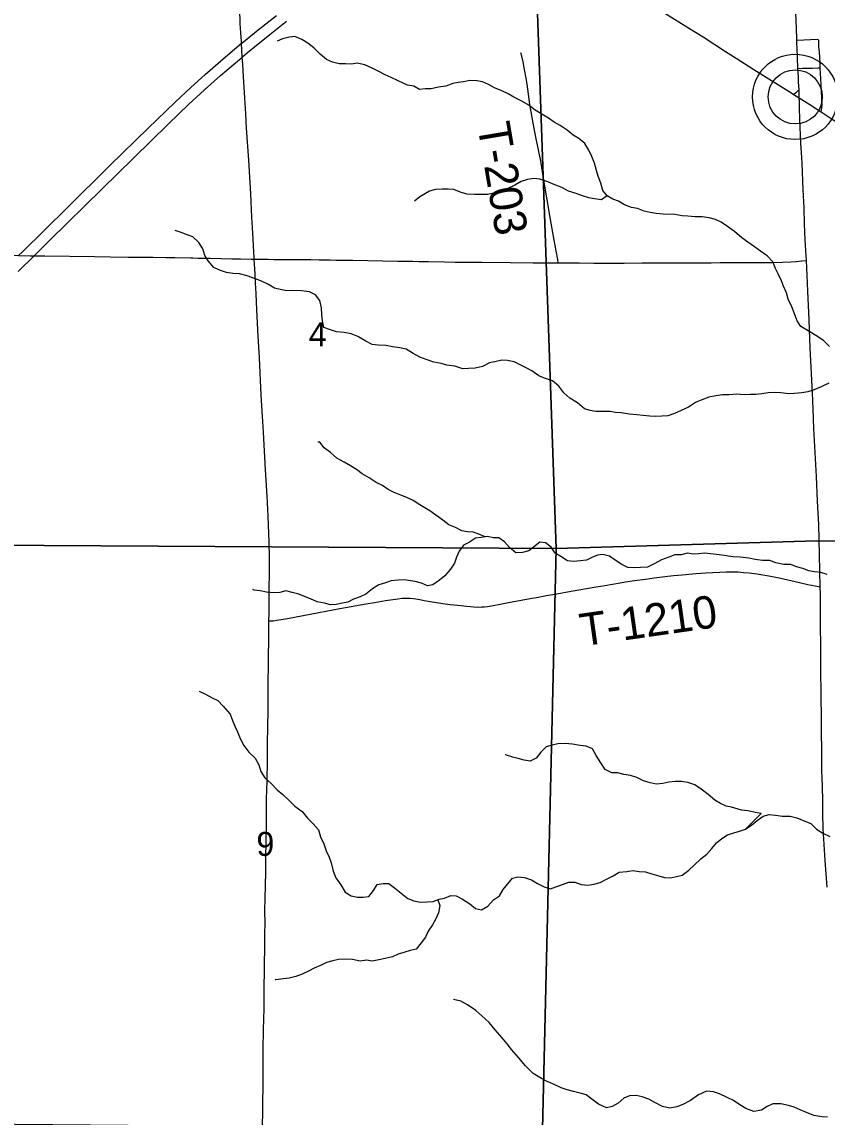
# Model space of a CAD drawing. Extents: x 0 to 34, y 0 to 22.
# Drawn here: x 13.666 to 15.07, y 11.289 to 13.199 of the extents above; entities that cross this region are included whole.
import ezdxf

# ---------------------------------------------------------------- set-up
doc = ezdxf.new("R2010")
doc.units = 0
for name, color, linetype in [('GM_X_County_Road', 7, 'Continuous'), ('GM_X_Interstate_Route', 7, 'Continuous'), ('GM_X_Minor_River', 7, 'Continuous'), ('GM_X_Section', 7, 'Continuous'), ('GM_X_Section_Text', 7, 'Continuous'), ('GM_X_State_Route', 7, 'Continuous'), ('GM_X_Township_Road', 7, 'Continuous'), ('GM_X_Township_Road_Text', 7, 'Continuous'), ('GM_X_Unincorporated', 7, 'Continuous'), ('GM_X_Unincorporated_Location', 7, 'Continuous')]:
    doc.layers.add(name, color=color, linetype=linetype)

msp = doc.modelspace()

# ---------------------------------------------------------------- linework, layer by layer
at = {"layer": 'GM_X_County_Road'}
msp.add_line((15.0217, 13.066), (15.0214, 13.0811), dxfattribs=at)
for points in [[(15.0175, 13.1667), (15.0173, 13.1721), (15.0166, 13.1852), (15.016, 13.2036), (15.015, 13.2225), (15.0142, 13.2429), (15.0126, 13.2796), (15.0123, 13.2934), (15.0124, 13.3029)], [(14.0708, 12.7856), (14.0707, 12.7876), (14.0685, 12.831), (14.0669, 12.8589), (14.0649, 12.8993), (14.0614, 12.9582), (14.0576, 13.0139), (14.0561, 13.0387), (14.0544, 13.0666), (14.052, 13.1034), (14.0508, 13.1253), (14.0499, 13.1379), (14.0498, 13.1387), (14.0488, 13.1608), (14.0487, 13.1619), (14.0485, 13.1658), (14.0475, 13.1804), (14.0465, 13.1967), (14.0456, 13.2216)], [(15.0193, 13.118), (15.0187, 13.1376), (15.0182, 13.1527), (15.0177, 13.1623), (15.0175, 13.1667)], [(15.0214, 13.0811), (15.0206, 13.0943), (15.0201, 13.1028), (15.0193, 13.118)], [(15.0113, 13.0726), (15.0151, 13.0753), (15.0171, 13.0767), (15.0188, 13.0785), (15.0214, 13.0811)], [(15.0342, 12.7829), (15.0337, 12.7914), (15.0322, 12.8194), (15.031, 12.8473), (15.03, 12.8752), (15.0285, 12.9063), (15.0265, 12.9528), (15.0254, 12.9714), (15.0246, 12.9869), (15.0227, 13.0303), (15.0221, 13.0488), (15.0218, 13.0612), (15.0217, 13.066)], [(14.0965, 12.1546), (14.0967, 12.1671), (14.0967, 12.1857), (14.0971, 12.2075), (14.0976, 12.2416), (14.0977, 12.2665), (14.0971, 12.2913), (14.095, 12.3375), (14.0935, 12.3719), (14.0904, 12.4183), (14.087, 12.4836), (14.0853, 12.5115), (14.0832, 12.5485), (14.0798, 12.6132), (14.0777, 12.651), (14.0754, 12.6973), (14.074, 12.7256), (14.073, 12.7442), (14.0722, 12.7597), (14.0708, 12.7856)], [(15.0583, 12.2138), (15.0571, 12.27), (15.0556, 12.3228), (15.0536, 12.3632), (15.0516, 12.4066), (15.0473, 12.4904), (15.0458, 12.5245), (15.0446, 12.5525), (15.0409, 12.6301), (15.0388, 12.6797), (15.0365, 12.7294), (15.0353, 12.7573), (15.0342, 12.7829)], [(15.0704, 11.6906), (15.0668, 11.737), (15.0646, 11.7743), (15.0634, 11.7926), (15.063, 11.8176), (15.0628, 11.8393), (15.062, 11.8675), (15.0617, 11.8796), (15.0613, 11.895), (15.061, 11.9106), (15.0611, 11.923), (15.061, 11.9292), (15.0609, 11.9354), (15.0608, 11.9384), (15.0605, 11.9505), (15.0604, 11.9594), (15.0602, 11.9842), (15.0601, 12.0246), (15.0595, 12.0712), (15.0594, 12.0992), (15.059, 12.1582), (15.0586, 12.2017), (15.0583, 12.2138)], [(14.0854, 11.2733), (14.0858, 11.2997), (14.0861, 11.3183), (14.0862, 11.34), (14.0863, 11.3555), (14.0866, 11.4079), (14.0871, 11.4418), (14.0875, 11.4603), (14.0879, 11.479), (14.0882, 11.5037), (14.0884, 11.5192), (14.0887, 11.5408), (14.0889, 11.5594), (14.0892, 11.581), (14.0895, 11.609), (14.0897, 11.6275), (14.0895, 11.6492), (14.0897, 11.6709), (14.0903, 11.6927), (14.0909, 11.7175), (14.091, 11.7298), (14.0911, 11.7452), (14.0911, 11.7512), (14.0914, 11.7603), (14.0917, 11.7758), (14.092, 11.7943), (14.092, 11.8065), (14.092, 11.8176), (14.092, 11.8251), (14.092, 11.8333), (14.0925, 11.8425), (14.0931, 11.861), (14.0934, 11.8734), (14.0937, 11.9138), (14.0941, 11.9417), (14.0944, 11.9695), (14.0949, 12.0003), (14.095, 12.028), (14.0951, 12.0373), (14.0958, 12.0868), (14.0962, 12.1269), (14.0964, 12.1464), (14.0965, 12.1546)]]:
    msp.add_lwpolyline(points, dxfattribs=at)
at = {"layer": 'GM_X_Interstate_Route'}
for points in [[(13.6592, 12.7639), (13.687, 12.7913), (13.7145, 12.8185), (13.8053, 12.9079), (13.8608, 12.9623), (13.9206, 13.0211), (13.9566, 13.0555), (13.984, 13.0809), (14.012, 13.1056), (14.045, 13.1339), (14.0499, 13.1379), (14.0506, 13.1386), (14.0593, 13.1459), (14.0712, 13.1559), (14.0978, 13.1775), (14.1273, 13.2004)], [(13.6597, 12.7919), (13.6663, 12.7984), (13.7439, 12.8746), (13.8192, 12.9488), (13.886, 13.0138), (13.9329, 13.0591), (13.9601, 13.0846), (13.9855, 13.1075), (14.0205, 13.1381), (14.0487, 13.1619), (14.0494, 13.1624), (14.0779, 13.1856), (14.1097, 13.2105)]]:
    msp.add_lwpolyline(points, dxfattribs=at)
at = {"layer": 'GM_X_Minor_River'}
for points in [[(15.0745, 12.6332), (15.064, 12.6436), (15.0508, 12.6521), (15.0399, 12.659), (15.0245, 12.6683), (15.0181, 12.6782), (15.0125, 12.6919), (15.0085, 12.7022), (15.0025, 12.7159), (14.9992, 12.7266), (14.994, 12.7384), (14.9907, 12.7479), (14.9855, 12.7589), (14.9803, 12.7692), (14.9758, 12.781), (14.9657, 12.791), (14.954, 12.7995), (14.9435, 12.8068), (14.9322, 12.8149), (14.9213, 12.8226), (14.9089, 12.8337), (14.8964, 12.8422), (14.8855, 12.8502), (14.8757, 12.8545), (14.8644, 12.8573), (14.8523, 12.8593), (14.8398, 12.8594), (14.8273, 12.8603), (14.8175, 12.8611), (14.8046, 12.8632), (14.7842, 12.8637), (14.7721, 12.865), (14.7615, 12.867), (14.7513, 12.8694), (14.7392, 12.874), (14.729, 12.8757), (14.7165, 12.88), (14.7063, 12.8865), (14.6962, 12.89), (14.6864, 12.8958), (14.6789, 12.9054), (14.6756, 12.9179), (14.6711, 12.9305), (14.6678, 12.94), (14.6645, 12.9529), (14.6597, 12.9644), (14.6545, 12.9758), (14.6478, 12.9873), (14.6372, 12.9961), (14.6274, 13.0015), (14.6165, 13.0107), (14.6048, 13.0184), (14.5943, 13.0246), (14.5841, 13.0315), (14.5608, 13.0454), (14.5499, 13.0539), (14.5363, 13.0616), (14.5235, 13.0681), (14.5137, 13.0736), (14.5027, 13.079), (14.4899, 13.0844), (14.4794, 13.0898), (14.4688, 13.0945), (14.459, 13.0965), (14.4472, 13.097), (14.4362, 13.0948), (14.4268, 13.0938), (14.4173, 13.0916), (14.4051, 13.0871), (14.3922, 13.0857), (14.3793, 13.0825), (14.3691, 13.0826), (14.3593, 13.0815), (14.3491, 13.0869), (14.3385, 13.0889), (14.3219, 13.0963), (14.3098, 13.1021), (14.2993, 13.1068), (14.2868, 13.1133), (14.2766, 13.1187), (14.2638, 13.1242), (14.2506, 13.127), (14.2403, 13.1255), (14.2301, 13.126), (14.2188, 13.1261), (14.2071, 13.1293), (14.1969, 13.1339), (14.1856, 13.1428), (14.1747, 13.1539), (14.1645, 13.1623), (14.154, 13.1685), (14.1419, 13.1736), (14.1321, 13.1725), (14.1203, 13.17), (14.1108, 13.1659)], [(14.6864, 12.8958), (14.6768, 12.8891), (14.6647, 12.8907), (14.6545, 12.8927), (14.6436, 12.8962), (14.6326, 12.9001), (14.619, 12.9041), (14.6073, 12.9106), (14.5953, 12.9153), (14.5828, 12.9203), (14.5692, 12.925), (14.5586, 12.9263), (14.5476, 12.9245), (14.5366, 12.9212), (14.5252, 12.9145), (14.5134, 12.9085), (14.5024, 12.9048), (14.4918, 12.9011), (14.4777, 12.8982), (14.466, 12.898), (14.455, 12.8981), (14.4425, 12.8986), (14.4319, 12.9017), (14.4191, 12.9071), (14.4093, 12.9076), (14.3987, 12.9073), (14.3869, 12.9067), (14.3767, 12.9038), (14.3599, 12.8941), (14.3504, 12.8869)], [(14.2658, 12.6423), (14.2515, 12.6504), (14.2398, 12.6554), (14.2277, 12.6574), (14.2144, 12.6587), (14.2039, 12.6622), (14.1925, 12.6665), (14.19, 12.6779), (14.1889, 12.6885), (14.1879, 12.7007), (14.185, 12.7132), (14.1775, 12.7232), (14.1673, 12.7286), (14.1533, 12.7302), (14.1382, 12.7308), (14.1276, 12.7301), (14.1158, 12.7325), (14.106, 12.7349), (14.0958, 12.7411), (14.0834, 12.7469), (14.0728, 12.7511), (14.0585, 12.7562), (14.0453, 12.7601), (14.0335, 12.7606), (14.0222, 12.7623), (14.012, 12.7658), (14.0003, 12.7708), (13.9902, 12.7823), (13.9849, 12.7918), (13.9809, 12.8033), (13.9742, 12.8143), (13.964, 12.8243), (13.9538, 12.8282), (13.9436, 12.8317), (13.9331, 12.8356)], [(15.0732, 12.5691), (15.0599, 12.5628), (15.0462, 12.5572), (15.0364, 12.5543), (15.0261, 12.5525), (15.0136, 12.5511), (15.0034, 12.5508), (14.9894, 12.5521), (14.9784, 12.553), (14.9674, 12.5523), (14.9564, 12.5505), (14.9458, 12.5495), (14.9356, 12.5496), (14.9258, 12.5489), (14.9129, 12.5498), (14.8996, 12.5488), (14.8875, 12.5489), (14.8761, 12.5471), (14.864, 12.5446), (14.8515, 12.5402), (14.8404, 12.5353), (14.8286, 12.5275), (14.8157, 12.5215), (14.8039, 12.5163), (14.7922, 12.5123), (14.7819, 12.5116), (14.7706, 12.511), (14.7607, 12.5118), (14.7494, 12.5131), (14.7384, 12.5139), (14.7252, 12.5152), (14.7112, 12.5176), (14.7013, 12.5181), (14.6915, 12.5197), (14.6669, 12.52), (14.6571, 12.5216), (14.6472, 12.5243), (14.6348, 12.5347), (14.6216, 12.5432), (14.6111, 12.5524), (14.6025, 12.5638), (14.5912, 12.5734), (14.5773, 12.5781), (14.5671, 12.582), (14.555, 12.5905), (14.5452, 12.5959), (14.5347, 12.6013), (14.5241, 12.6063), (14.5124, 12.6087), (14.5025, 12.6092), (14.4908, 12.6063), (14.4813, 12.6049), (14.4688, 12.5982), (14.4562, 12.5952), (14.4445, 12.5946), (14.4346, 12.5943), (14.421, 12.599), (14.4067, 12.6007), (14.3968, 12.6034), (14.384, 12.6058), (14.3723, 12.6097), (14.3595, 12.6144), (14.3482, 12.621), (14.3357, 12.6283), (14.3248, 12.6311), (14.3123, 12.6327), (14.3009, 12.6351), (14.2873, 12.6356), (14.2767, 12.6368), (14.2658, 12.6423)], [(14.4738, 12.3012), (14.4625, 12.3057), (14.4527, 12.3092), (14.4428, 12.31), (14.433, 12.3116), (14.4217, 12.3174), (14.4104, 12.3221), (14.3998, 12.3302), (14.3878, 12.339), (14.3769, 12.3467), (14.3595, 12.3571), (14.3483, 12.3648), (14.3373, 12.3699), (14.3267, 12.3738), (14.315, 12.3784), (14.3045, 12.3839), (14.2947, 12.3908), (14.2834, 12.3958), (14.2713, 12.4039), (14.2593, 12.4112), (14.2495, 12.4185), (14.2389, 12.4251), (14.228, 12.4313), (14.2148, 12.4382), (14.2039, 12.4482), (14.193, 12.4567), (14.1852, 12.4662), (14.1817, 12.4666)], [(15.0704, 12.2356), (15.0591, 12.2388), (15.0485, 12.24), (15.0386, 12.242), (15.0281, 12.2459), (15.0167, 12.2487), (15.0069, 12.2529), (14.9948, 12.253), (14.9808, 12.2558), (14.9706, 12.2601), (14.9578, 12.2599), (14.9449, 12.2619), (14.9336, 12.2643), (14.9184, 12.2659), (14.9059, 12.2664), (14.895, 12.2684), (14.8817, 12.2697), (14.8666, 12.2714), (14.8564, 12.2726), (14.8465, 12.2719), (14.8363, 12.2713), (14.8265, 12.2729), (14.8158, 12.27), (14.8045, 12.2697), (14.7942, 12.266), (14.7813, 12.2612), (14.7695, 12.2545), (14.757, 12.2485), (14.7445, 12.2479), (14.7342, 12.2472), (14.7225, 12.2477), (14.7119, 12.2528), (14.7007, 12.2605), (14.6905, 12.2678), (14.6792, 12.2705), (14.6697, 12.2695), (14.6598, 12.2654), (14.6503, 12.2606), (14.6393, 12.2592), (14.6279, 12.2585), (14.6173, 12.2594), (14.606, 12.2667), (14.5959, 12.2729), (14.5888, 12.2832), (14.579, 12.2909), (14.5688, 12.2921), (14.5497, 12.2771), (14.5391, 12.2742), (14.527, 12.2735), (14.5161, 12.2824), (14.5074, 12.2923), (14.4973, 12.2996), (14.4874, 12.2997), (14.4776, 12.3017), (14.467, 12.3003), (14.4571, 12.2989), (14.4461, 12.2922), (14.4362, 12.2866), (14.4282, 12.276), (14.4235, 12.2658)], [(14.4235, 12.2658), (14.4204, 12.2552), (14.4131, 12.2451), (14.4036, 12.233), (14.394, 12.2259), (14.3826, 12.2176), (14.3731, 12.2158), (14.3629, 12.2205), (14.3516, 12.2236), (14.3319, 12.2261), (14.3217, 12.2258), (14.31, 12.2248), (14.2997, 12.2211), (14.2883, 12.2174), (14.2773, 12.2107), (14.2658, 12.2013), (14.2556, 12.1965), (14.2438, 12.1924), (14.2343, 12.1872), (14.2248, 12.1858), (14.2138, 12.1832), (14.204, 12.1826), (14.1934, 12.1853), (14.1809, 12.1877), (14.1692, 12.1932), (14.1586, 12.1974), (14.1484, 12.2013), (14.1371, 12.2041), (14.1262, 12.2072), (14.1155, 12.2039), (14.1053, 12.2037), (14.0924, 12.2049), (14.0811, 12.2073), (14.0705, 12.2082), (14.0686, 12.2097)], [(13.9747, 12.0319), (13.986, 12.0269), (13.9973, 12.0203), (14.0075, 12.0156), (14.0165, 12.0061), (14.0289, 11.9919), (14.033, 11.9809), (14.0371, 11.9713), (14.0415, 11.9614), (14.0463, 11.9496), (14.0527, 11.9374), (14.0617, 11.9259), (14.0722, 11.9152), (14.0789, 11.9034), (14.0826, 11.892), (14.0893, 11.8809), (14.1002, 11.8709), (14.1107, 11.8602), (14.1209, 11.8518), (14.131, 11.8418), (14.1415, 11.8318), (14.1543, 11.8222), (14.1637, 11.8104), (14.1738, 11.8008), (14.1832, 11.7904), (14.1865, 11.7779), (14.1925, 11.7657), (14.1965, 11.7539), (14.2013, 11.7424), (14.2051, 11.7325), (14.2087, 11.7181), (14.2132, 11.7067), (14.2221, 11.6941), (14.2292, 11.6815), (14.2402, 11.6753), (14.2511, 11.6729), (14.261, 11.6728), (14.2708, 11.6742), (14.2789, 11.6844), (14.2854, 11.695), (14.296, 11.6967), (14.3059, 11.6967), (14.3156, 11.6893), (14.3269, 11.6801), (14.3386, 11.6705), (14.3495, 11.6663), (14.3609, 11.6642), (14.3726, 11.6645), (14.3832, 11.6655), (14.3935, 11.6692), (14.4029, 11.671), (14.4136, 11.6759), (14.4234, 11.6754), (14.4344, 11.6692), (14.4468, 11.6611), (14.4566, 11.6534), (14.4671, 11.6507), (14.4782, 11.657), (14.4881, 11.6683), (14.4988, 11.675), (14.5053, 11.686), (14.5134, 11.6961), (14.5214, 11.7059), (14.5309, 11.7085), (14.5422, 11.7069), (14.5547, 11.703), (14.5649, 11.6968), (14.5769, 11.691), (14.5875, 11.6875), (14.597, 11.6908), (14.6088, 11.6952), (14.6198, 11.6993), (14.63, 11.6988), (14.6409, 11.6949), (14.6531, 11.6936), (14.6633, 11.6954), (14.6743, 11.6984), (14.6853, 11.7043), (14.6971, 11.7103), (14.7074, 11.7163), (14.7207, 11.7177), (14.7313, 11.7191), (14.7426, 11.7174), (14.7532, 11.717), (14.7642, 11.7134), (14.7766, 11.7103), (14.7865, 11.7071), (14.797, 11.7063), (14.8077, 11.7088), (14.8172, 11.711), (14.829, 11.72), (14.8385, 11.7286), (14.85, 11.7395), (14.8606, 11.7478), (14.8691, 11.7576), (14.8771, 11.7677), (14.8866, 11.7749), (14.8965, 11.7816), (14.9075, 11.7849), (14.9174, 11.7878), (14.928, 11.7915)], [(14.928, 11.7915), (14.9555, 11.8186), (14.9449, 11.8206), (14.9328, 11.8233), (14.9211, 11.8246), (14.9037, 11.8301), (14.8939, 11.8317), (14.8841, 11.836), (14.8743, 11.8421), (14.863, 11.8517), (14.8506, 11.861), (14.8393, 11.8687), (14.8272, 11.8726), (14.8163, 11.8746), (14.8053, 11.8743), (14.7943, 11.8733), (14.7837, 11.8711), (14.7727, 11.8701), (14.7614, 11.8725), (14.75, 11.8756), (14.7383, 11.8814), (14.7274, 11.8849), (14.7157, 11.8869), (14.7051, 11.8897), (14.6945, 11.8898), (14.6832, 11.8956), (14.6753, 11.9071), (14.6675, 11.92), (14.6611, 11.9315), (14.6502, 11.9361), (14.6392, 11.9374), (14.626, 11.9398), (14.6131, 11.9411), (14.6002, 11.9404), (14.5904, 11.9382), (14.5801, 11.9353), (14.5706, 11.9259), (14.5625, 11.915), (14.5523, 11.9102), (14.5417, 11.9118), (14.5315, 11.9149), (14.5217, 11.9173), (14.5092, 11.9212), (14.5084, 11.9212)], [(14.928, 11.7915), (14.9383, 11.7983), (14.9482, 11.8065), (14.9585, 11.814), (14.9691, 11.8173), (14.9801, 11.8161), (14.9922, 11.814), (15.0058, 11.8139), (15.0176, 11.8115), (15.0315, 11.8053), (15.0417, 11.8014), (15.0518, 11.7915), (15.0628, 11.7845), (15.0748, 11.7787)], [(14.3914, 11.6685), (14.3949, 11.6586), (14.3925, 11.6457), (14.3879, 11.6351), (14.3817, 11.6246), (14.3744, 11.6136), (14.3694, 11.6034), (14.3618, 11.5933), (14.3533, 11.5824), (14.3431, 11.5798), (14.3321, 11.5765), (14.3222, 11.5735), (14.312, 11.5687), (14.2994, 11.5662), (14.2884, 11.5636), (14.2767, 11.5611), (14.2665, 11.5631), (14.2555, 11.5613), (14.2422, 11.5641), (14.2305, 11.5646), (14.218, 11.5639), (14.2078, 11.5621), (14.1968, 11.5588), (14.1865, 11.554), (14.1751, 11.5492), (14.1656, 11.5436), (14.1546, 11.5384), (14.1432, 11.5343), (14.1318, 11.5314), (14.1212, 11.5304), (14.1087, 11.5286), (14.1072, 11.5297)], [(15.0707, 11.2894), (15.0613, 11.2897), (15.0472, 11.2923), (15.0343, 11.2972), (15.0233, 11.3021), (15.0127, 11.3067), (15.0028, 11.3097), (14.9895, 11.3127), (14.9755, 11.3126), (14.9656, 11.3077), (14.9558, 11.3012), (14.9425, 11.2992), (14.9285, 11.3045), (14.9182, 11.3109), (14.9068, 11.3181), (14.8958, 11.3238), (14.8825, 11.3302), (14.8718, 11.3335), (14.8597, 11.3346), (14.8457, 11.3282), (14.8321, 11.3182), (14.8184, 11.3114), (14.8078, 11.3075), (14.7961, 11.3052), (14.7828, 11.3079), (14.7699, 11.3146), (14.7592, 11.3207), (14.7478, 11.3248), (14.7372, 11.3271), (14.7254, 11.3267), (14.7156, 11.3221), (14.7058, 11.3137), (14.6952, 11.308), (14.6853, 11.3053), (14.6716, 11.3117), (14.6598, 11.3208), (14.65, 11.3279), (14.6393, 11.3313), (14.6279, 11.3339), (14.6169, 11.3369), (14.6063, 11.3403), (14.5915, 11.3471), (14.5816, 11.3513), (14.5717, 11.3569), (14.5573, 11.3656), (14.544, 11.3788), (14.5318, 11.3932), (14.5196, 11.4072), (14.512, 11.4171), (14.5032, 11.4273), (14.4914, 11.4417), (14.4804, 11.4545), (14.4678, 11.4659), (14.4572, 11.4753), (14.4428, 11.4851), (14.4314, 11.4916), (14.4185, 11.4946)]]:
    msp.add_lwpolyline(points, dxfattribs=at)
at = {"layer": 'GM_X_Section'}
for points in [[(14.5623, 13.2983), (14.5977, 12.2808), (13.6043, 12.2869), (13.5746, 13.3006), (14.5077, 13.2997)], [(15.5625, 13.3022), (15.5907, 12.2877), (15.0525, 12.2941), (14.5977, 12.2808), (14.5623, 13.2983), (15.5148, 13.3016)], [(13.6043, 12.2869), (14.5977, 12.2808), (14.5738, 11.2682), (13.5876, 11.2769)], [(15.5907, 12.2877), (15.569, 11.2675), (14.5738, 11.2682), (14.5977, 12.2808), (15.0525, 12.2941)]]:
    msp.add_lwpolyline(points, close=True, dxfattribs=at)
at = {"layer": 'GM_X_State_Route'}
msp.add_lwpolyline([(15.2517, 12.9528), (15.2161, 12.964), (15.1955, 12.971), (15.1781, 12.9775), (15.1637, 12.9835), (15.1468, 12.9912), (15.1302, 12.9996), (15.1139, 13.0086), (15.0925, 13.0211), (15.0793, 13.0292), (15.0599, 13.0418), (15.0533, 13.046), (15.0401, 13.0544), (15.0217, 13.066), (15.0113, 13.0726), (15.0086, 13.0743), (14.9902, 13.0858), (14.9638, 13.1022), (14.9427, 13.1154), (14.9114, 13.1354), (14.893, 13.147), (14.854, 13.1724), (14.8304, 13.1873), (14.7856, 13.2152)], dxfattribs=at)
at = {"layer": 'GM_X_Township_Road'}
for points in [[(15.0583, 13.1192), (15.0581, 13.1273), (15.057, 13.1471), (15.056, 13.1553), (15.0559, 13.1656), (15.0559, 13.1665), (15.0556, 13.1673), (15.0547, 13.168), (15.0534, 13.1683), (15.0175, 13.1667)], [(14.6013, 12.7789), (14.6003, 12.7848), (14.5977, 12.8001), (14.5942, 12.8184), (14.587, 12.8582), (14.5816, 12.8888), (14.5771, 12.9164), (14.5737, 12.9378), (14.5706, 12.9562), (14.5663, 12.9788), (14.5626, 12.9955), (14.558, 13.0198), (14.5518, 13.0552), (14.5493, 13.0731), (14.5472, 13.0909), (14.5453, 13.1011), (14.5426, 13.116), (14.54, 13.1298), (14.5376, 13.1392), (14.536, 13.1452)], [(15.0193, 13.118), (15.0276, 13.1184), (15.0366, 13.1185), (15.0449, 13.1187), (15.0547, 13.1191), (15.0583, 13.1192)], [(15.0599, 13.0418), (15.0607, 13.0463), (15.061, 13.0494), (15.0614, 13.0544), (15.0613, 13.0601), (15.0611, 13.0664), (15.0606, 13.0776), (15.0599, 13.0896), (15.0591, 13.0997), (15.0585, 13.1097), (15.0583, 13.1192)], [(13.4884, 12.7885), (13.5001, 12.7889), (13.5374, 12.7908), (13.5622, 12.7917), (13.5933, 12.7926), (13.6182, 12.7927), (13.6431, 12.7922), (13.6597, 12.7919), (13.6804, 12.7914), (13.687, 12.7913), (13.7053, 12.7911), (13.7923, 12.7901), (13.8202, 12.7897), (13.8513, 12.7892), (13.8642, 12.789)], [(13.8642, 12.789), (13.8948, 12.7887), (13.9166, 12.7885), (13.9322, 12.7884), (13.9601, 12.7877), (13.9639, 12.7876)], [(13.9639, 12.7876), (13.9725, 12.7874), (13.9943, 12.787), (14.0129, 12.7866), (14.0315, 12.7862), (14.0471, 12.7859), (14.0656, 12.7856), (14.0687, 12.7855), (14.0708, 12.7856)], [(14.0708, 12.7856), (14.0859, 12.7853), (14.0952, 12.7852), (14.1044, 12.7851), (14.1106, 12.785), (14.123, 12.7848), (14.1354, 12.7851), (14.1477, 12.7849), (14.1695, 12.7849), (14.1844, 12.7843), (14.1953, 12.7843), (14.2032, 12.7842), (14.2131, 12.784), (14.2431, 12.7835), (14.3211, 12.7822), (14.3473, 12.7818), (14.3579, 12.7815), (14.3749, 12.7814), (14.4026, 12.7808), (14.4212, 12.7803), (14.4677, 12.78), (14.5173, 12.7799), (14.5577, 12.7793), (14.5729, 12.7791), (14.6013, 12.7789)], [(14.6013, 12.7789), (14.6384, 12.7789), (14.6632, 12.7786), (14.6819, 12.7785), (14.716, 12.7786), (14.7471, 12.7789), (14.7843, 12.7792), (14.8185, 12.7793), (14.8682, 12.7793), (14.8837, 12.7794), (14.9147, 12.7795), (14.9519, 12.7798), (14.9736, 12.7799), (14.9925, 12.7805), (15.007, 12.781), (15.0164, 12.7816), (15.026, 12.7823), (15.0342, 12.7829)], [(14.5688, 12.1967), (14.5808, 12.1989), (14.5989, 12.2021), (14.6237, 12.2067), (14.6674, 12.2142), (14.6826, 12.2166), (14.709, 12.2211), (14.7188, 12.2228), (14.7343, 12.2251), (14.7533, 12.2276), (14.7684, 12.2296), (14.8021, 12.2336), (14.8175, 12.2352), (14.8411, 12.2374), (14.8588, 12.2383), (14.8831, 12.2395), (14.8943, 12.24), (14.9062, 12.2403), (14.9152, 12.2401), (14.9246, 12.2393), (14.9344, 12.2385), (14.9484, 12.2367), (14.958, 12.2351), (14.9687, 12.2331), (14.9865, 12.2295), (15.0223, 12.2214), (15.0369, 12.2183), (15.0497, 12.2156), (15.0583, 12.2138)], [(14.0965, 12.1546), (14.1039, 12.155), (14.1104, 12.1558), (14.1287, 12.159), (14.1562, 12.1641), (14.1836, 12.1694), (14.2203, 12.1762), (14.2662, 12.1843), (14.2806, 12.1868), (14.2996, 12.19), (14.3214, 12.1934), (14.329, 12.1941), (14.3357, 12.1945), (14.3429, 12.1943), (14.3487, 12.1937), (14.3529, 12.193), (14.3599, 12.1918), (14.3673, 12.1904), (14.3776, 12.1884), (14.3888, 12.1866), (14.4, 12.185), (14.4127, 12.1835), (14.4317, 12.1814), (14.4414, 12.1801), (14.4481, 12.1795), (14.4537, 12.1791), (14.4606, 12.1788), (14.4676, 12.1789), (14.4725, 12.1792), (14.4778, 12.1796), (14.4875, 12.1813), (14.4996, 12.1836), (14.5143, 12.1865), (14.5524, 12.1936), (14.5668, 12.1963), (14.5688, 12.1967)]]:
    msp.add_lwpolyline(points, dxfattribs=at)
at = {"layer": 'GM_X_Unincorporated'}
for radius in [0.0744, 0.0472]:
    msp.add_circle((15.0146, 13.0685), radius, dxfattribs=at)
at = {"layer": 'GM_X_Unincorporated_Location'}
msp.add_line((15.0146, 13.0685), (15.0146, 13.0685), dxfattribs=at)

# ---------------------------------------------------------------- texts
at = {"layer": 'GM_X_Section_Text'}
for s, p in [('4', (14.1659, 12.6335)), ('9', (14.0747, 11.7449))]:
    msp.add_text(s, height=0.0419, rotation=0, dxfattribs=at).set_placement(p)
at = {"layer": 'GM_X_Township_Road_Text'}
for s, rotation, p in [('T-203', 279.5612, (14.4599, 13.0196)), ('T-1210', 8.1059, (14.643, 12.1102))]:
    msp.add_text(s, height=0.05682, rotation=rotation, dxfattribs=at).set_placement(p)

doc.saveas('drawing.dxf')
